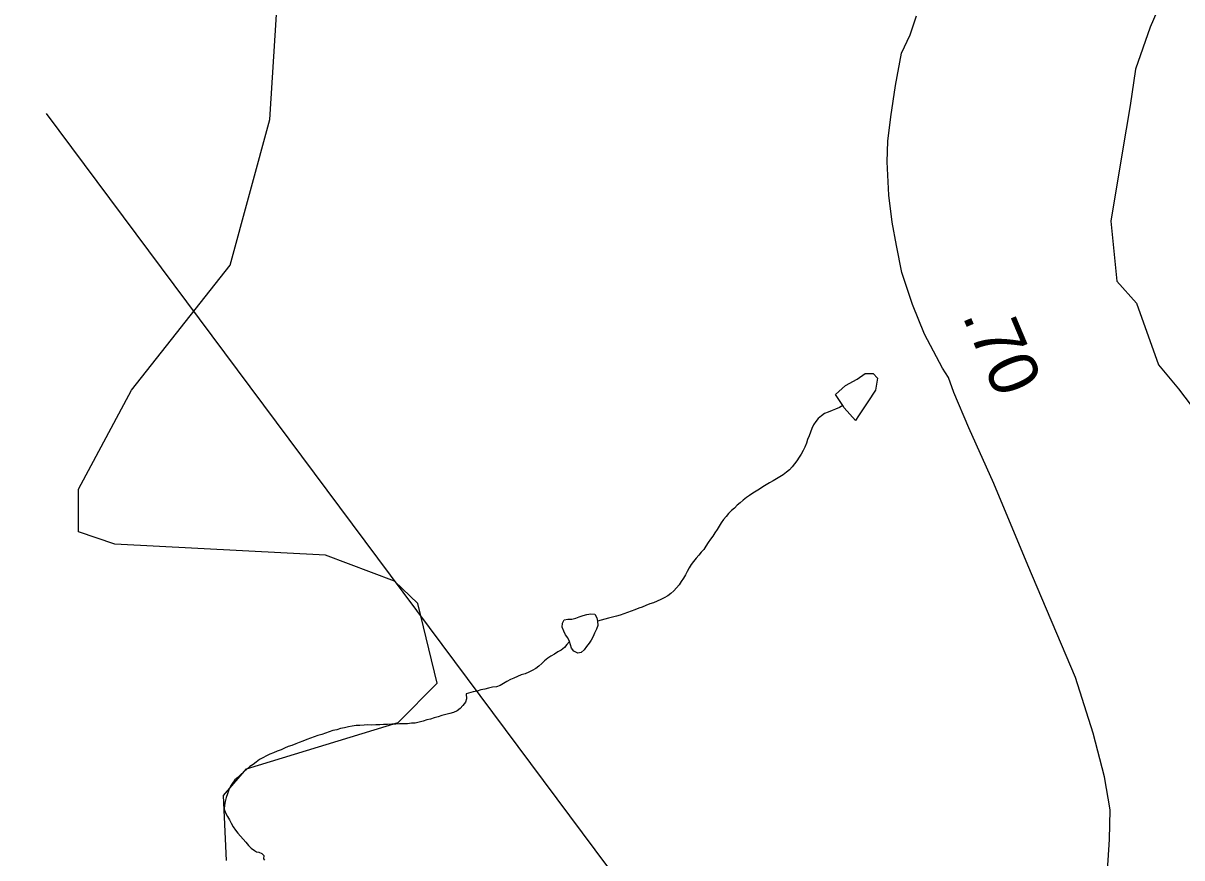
# Model space of a CAD drawing. Extents: x 1950930 to 2061844, y 904556 to 1017002.
# Drawn here: x 1984366 to 1987298, y 920553 to 922665 of the extents above; entities that cross this region are included whole.
import ezdxf

# ---------------------------------------------------------------- set-up
doc = ezdxf.new("R2010")
doc.units = 0
for name, color, linetype in [('Exist Hydrographic Creek Single Shore', 7, 'Continuous'), ('Exist Hydrographic Misc Water Feature', 7, 'Continuous'), ('Exist Road Primary NC Attributed', 7, 'Continuous'), ('Exist Road Primary NC Mileage Hundredths English Label', 7, 'Continuous'), ('Exist Road Secondary Mileage Hundredths English Label', 7, 'Continuous')]:
    doc.layers.add(name, color=color, linetype=linetype)

msp = doc.modelspace()

# ---------------------------------------------------------------- linework, layer by layer
at = {"layer": 'Exist Hydrographic Creek Single Shore'}
for points in [[(1984880.9, 920546.2), (1984872.9, 920710.5), (1984931, 920778.1), (1985315, 920894.9), (1985414.1, 920994.7), (1985365.1, 921196), (1985306, 921252.9), (1985131.1, 921318.9), (1984598, 921346.3), (1984506.1, 921377.7), (1984506.1, 921486), (1984640, 921736), (1984889.9, 922052.4), (1984990, 922421.2), (1985007, 922686.7), (1984932, 922737.5), (1984649, 922746.6), (1984566, 922794.3), (1984607, 923036.2), (1984599, 923177.5), (1984366, 923513.8)], [(1987269.2, 922777.6), (1987257.3, 922745.3), (1987218.2, 922655.1), (1987181.3, 922548.3), (1987168.1, 922456.5), (1987147.2, 922336.4), (1987118.5, 922163.8), (1987133.9, 922011.7), (1987184.1, 921956.5), (1987239.7, 921800.4), (1987290.4, 921739.6), (1987357, 921651.9), (1987383.2, 921588.2), (1987400.1, 921535.3)], [(1986440.2, 921697.1), (1986431.8, 921692.3), (1986422.2, 921688.5), (1986413.1, 921684.6), (1986403.5, 921680.8), (1986394.3, 921676.9), (1986386.1, 921671.3), (1986378.3, 921664.7), (1986372.3, 921656.7), (1986366.6, 921648.6), (1986362.3, 921639.6), (1986358.4, 921630), (1986354.9, 921620.8), (1986351.4, 921611.2), (1986348.3, 921602.3), (1986344, 921592.4), (1986339.7, 921583.3), (1986334.8, 921574.7), (1986329.7, 921566.6), (1986324.4, 921557.7), (1986318.4, 921549.7), (1986312.5, 921542), (1986305.3, 921535), (1986297.7, 921528.5), (1986289.5, 921522.4), (1986280.9, 921516.8), (1986272.5, 921512), (1986263.9, 921506.4), (1986255, 921501.6), (1986246.6, 921496.9), (1986237.6, 921491.3), (1986229.4, 921485.6), (1986221, 921480.9), (1986212.4, 921475.3), (1986204.4, 921470), (1986196.6, 921464.3), (1986188.2, 921457.8), (1986180.8, 921451.3), (1986173, 921445.1), (1986165.9, 921437.7), (1986158.5, 921431.5), (1986151.3, 921424.1), (1986144.9, 921416.9), (1986138.6, 921409), (1986132.8, 921400.9), (1986127.5, 921392), (1986122.4, 921383.8), (1986116.6, 921375), (1986111.1, 921366.9), (1986105.6, 921358.8), (1986099.8, 921350.4), (1986094.1, 921341.5), (1986088.5, 921333.4), (1986082.2, 921326.2), (1986075.8, 921318.3), (1986069.5, 921311.1), (1986062.5, 921302.8), (1986056.6, 921294.8), (1986051.8, 921286.6), (1986046.5, 921277.7), (1986042, 921269), (1986037.3, 921260.1), (1986031.5, 921252), (1986026, 921243.9), (1986019.7, 921236), (1986012.5, 921228.5), (1986005.3, 921221.8), (1985997.5, 921215.8), (1985988.7, 921210.9), (1985979.5, 921206.3), (1985970.2, 921202.4), (1985961, 921198.1), (1985951.6, 921195.2), (1985942.3, 921191.3), (1985932.9, 921187.4), (1985923.9, 921184.3), (1985914.3, 921180.5), (1985904.8, 921177.4), (1985895.8, 921173.6), (1985886.2, 921170.1), (1985876.7, 921167.2), (1985867.3, 921164.1), (1985857.7, 921161.9), (1985847.8, 921159), (1985838.2, 921156.8), (1985819.5, 921151.9)], [(1985748.4, 921100.2), (1985742, 921093), (1985735.7, 921084.7), (1985727.9, 921078.6), (1985719.2, 921073.8), (1985710.6, 921068.2), (1985701.8, 921063.4), (1985693.6, 921057.8), (1985685.8, 921051.3), (1985678.6, 921044.2), (1985671.3, 921037.7), (1985663.1, 921031.6), (1985654.5, 921026.8), (1985645.4, 921022.5), (1985636.2, 921018.6), (1985626.8, 921015.6), (1985617.1, 921011.7), (1985608.1, 921007.9), (1985599.3, 921003.9), (1985590.5, 920999.2), (1985581.5, 920993.7), (1985573, 920988.9), (1985563.6, 920985.8), (1985554, 920984.5), (1985543.7, 920982), (1985534.1, 920979.7), (1985524.4, 920977.6), (1985515, 920974.6), (1985504.8, 920972.5), (1985487.1, 920967.9)], [(1985487.1, 920967.9), (1985488.4, 920955.4), (1985485.7, 920946.5), (1985479.1, 920938.2), (1985472, 920931.1), (1985464.2, 920924.7), (1985455.3, 920920.7), (1985445.5, 920917.7), (1985435.9, 920915.6), (1985425.6, 920913.1), (1985416.2, 920910), (1985406.3, 920907.1), (1985396.9, 920904.1), (1985387.7, 920901.8), (1985378.2, 920898.7), (1985368, 920896.3), (1985358.4, 920894), (1985348.5, 920893.5), (1985338.9, 920892.2), (1985329, 920891.7), (1985318.8, 920891.6), (1985308.9, 920891.1), (1985298.7, 920891), (1985288.4, 920890.5), (1985278.2, 920890), (1985268.7, 920889.4), (1985258.5, 920889.4), (1985248.7, 920888.8), (1985238.6, 920889.2), (1985228.8, 920888.6), (1985218.3, 920887.8), (1985208.5, 920887.3), (1985198.4, 920885.9), (1985189, 920884.5), (1985179.1, 920881.9), (1985169.3, 920879.8), (1985159.5, 920876.8), (1985149.8, 920874.7), (1985140.4, 920871.6), (1985131, 920868.2), (1985121.5, 920865.1), (1985112.1, 920862.1), (1985102.7, 920859.1), (1985093, 920855.3), (1985083.6, 920852.2), (1985073.9, 920848), (1985064.9, 920844.9), (1985055.9, 920841), (1985046.3, 920837.2), (1985036.8, 920834.2), (1985027.8, 920830.3), (1985018.6, 920826.5), (1985008.9, 920822.6), (1984999.9, 920818.7), (1984990.7, 920814.8), (1984981.7, 920811), (1984972.7, 920806.2), (1984964.2, 920801.5), (1984955.6, 920795), (1984947.8, 920789.3), (1984939.6, 920783.6), (1984931.8, 920777.6), (1984924.3, 920770.2), (1984916.7, 920763.6), (1984909.7, 920756.5), (1984902.1, 920750), (1984895.8, 920742), (1984890.6, 920733.9), (1984886.1, 920724.9), (1984882.8, 920715.2), (1984879.4, 920705.5), (1984876.9, 920695.7), (1984875.7, 920685.8), (1984874.8, 920675.8), (1984878.1, 920666.7), (1984883.5, 920657.8), (1984887.8, 920648.7), (1984892.7, 920640.2), (1984897.6, 920631.4), (1984903.1, 920622.9), (1984909.5, 920615.4), (1984916.3, 920607.8), (1984923, 920600.3), (1984929.2, 920592.9), (1984936.2, 920583.7), (1984942.9, 920576.9), (1984951.1, 920571.7), (1984956.9, 920568.3), (1984962.6, 920567.5), (1984969.8, 920564), (1984974.9, 920559.1)]]:
    msp.add_lwpolyline(points, dxfattribs=at)
at = {"layer": 'Exist Hydrographic Misc Water Feature'}
for points in [[(1986440.2, 921697.1), (1986421.6, 921725.5), (1986447.4, 921748), (1986476.9, 921763.8), (1986497, 921778.1), (1986517.1, 921778.3), (1986528.6, 921766.4), (1986523.3, 921736.4), (1986503.4, 921706.6), (1986479.8, 921671.6), (1986472.2, 921659.4), (1986443.5, 921691.4), (1986440.2, 921697.1)], [(1985748.4, 921100.2), (1985744.3, 921109.3), (1985738.9, 921117.4), (1985734, 921126.8), (1985730.5, 921136.6), (1985730.9, 921146.7), (1985735, 921155.4), (1985744.3, 921156.8), (1985754.7, 921156.4), (1985764.6, 921159.1), (1985773.2, 921163), (1985783, 921165.9), (1985792.9, 921168.9), (1985803.1, 921170.6), (1985812.5, 921169.5), (1985817.9, 921160.3), (1985819.5, 921151.9)], [(1985819.5, 921151.9), (1985820.1, 921140.4), (1985816.9, 921131.6), (1985812.3, 921121.7), (1985808.2, 921113), (1985803.7, 921103.9), (1985798.2, 921095.9), (1985791.8, 921087.9), (1985785.7, 921079.5), (1985778.1, 921072.5), (1985769.5, 921071), (1985759.4, 921075.4), (1985754.1, 921083.5), (1985748.4, 921100.2)], [(1984974.9, 920559.1), (1984974.3, 920550.7), (1984976.6, 920546.7)]]:
    msp.add_lwpolyline(points, dxfattribs=at)
at = {"layer": 'Exist Road Primary NC Attributed'}
msp.add_lwpolyline([(1987110.6, 920520.4), (1987115.2, 920599.4), (1987116.7, 920673.9), (1987103, 920757.4), (1987074.2, 920868.4), (1987029.4, 921008.9), (1986908.7, 921293.8), (1986822.9, 921499.7), (1986759.1, 921641), (1986721.2, 921730.7), (1986707.5, 921768.7), (1986692.6, 921791.6), (1986647, 921877.6), (1986616.7, 921953.4), (1986589.9, 922033.8), (1986576.2, 922102.2), (1986565.6, 922161.5), (1986556.5, 922229.9), (1986552.7, 922314.2), (1986554.2, 922365.9), (1986561.8, 922428.2), (1986573.8, 922507.1), (1986589.1, 922589.2), (1986610.7, 922635.6), (1986626.5, 922683.8)], dxfattribs=at)
at = {"layer": 'Exist Road Secondary Mileage Hundredths English Label'}
msp.add_line((1986246.2, 919993.3), (1984424.8, 922436.7), dxfattribs=at)

# ---------------------------------------------------------------- texts
at = {"layer": 'Exist Road Primary NC Mileage Hundredths English Label'}
msp.add_text('.70', height=125, rotation=292.9461, dxfattribs=at).set_placement((1986741.7, 921925.1))

doc.saveas('drawing.dxf')
